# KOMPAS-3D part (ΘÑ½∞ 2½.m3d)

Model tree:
1. Эскиз:1
2. Операция выдавливания:1
     Расстояние 1 = 2
3. Эскиз:2
4. Операция выдавливания:2
     Расстояние 1 = 5
5. Эскиз:3
6. Операция выдавливания:3
     Расстояние 1 = 2
7. Эскиз:4
8. Операция выдавливания:4
     Расстояние 1 = 78
9. Эскиз:5
10. Операция выдавливания:5
     Расстояние 1 = 2
11. Эскиз:6
12. Операция выдавливания:6
     Расстояние 1 = 4.5
13. Эскиз:7
14. Операция выдавливания:7
     Расстояние 1 = 2
15. Скругление:1
     Радиус = 1
16. Скругление:2
     Радиус = 1
17. Эскиз:8
18. Вырезать элемент выдавливания:1
     Расстояние 1 = 10; Угол 1 = 35
19. Эскиз:9
20. Вырезать элемент выдавливания:2
     Расстояние 1 = 10; Угол 1 = 35
21. Эскиз:10
22. Вырезать элемент выдавливания:3
     Расстояние 2 = 22; Расстояние 1 = 22; Угол 1 = 35
23. Эскиз:11
24. Вырезать элемент выдавливания:4
     Расстояние 2 = 2; Расстояние 1 = 2
25. Эскиз:12
26. Вырезать элемент выдавливания:5
     Расстояние 2 = 2; Расстояние 1 = 2; Угол 1 = 35
27. Эскиз:13
28. Вырезать элемент выдавливания:6
     Расстояние 2 = 2; Расстояние 1 = 122
29. Эскиз:14
30. Вырезать элемент выдавливания:7
     Расстояние 2 = 100; Расстояние 1 = 60
